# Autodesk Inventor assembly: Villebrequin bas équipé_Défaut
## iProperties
Shininess: 64.0
Length Units: 11269
Angle Units: 11279
Time Units: 11290
Mass Units: 11283
Length Display Precision: 3
Angle Display Precision: 2
Compacted: True
Created: 2006-01
Part Number: Villebrequin bas équipé_Défaut
Document SubType Name: Assembly
Designer: riri
Density: 0.0
Volumn: 0.0
Area: 0.0
PropertySet Name: Model Information
Control State: 0
Master: False
Checked Out: False
Author: riri
